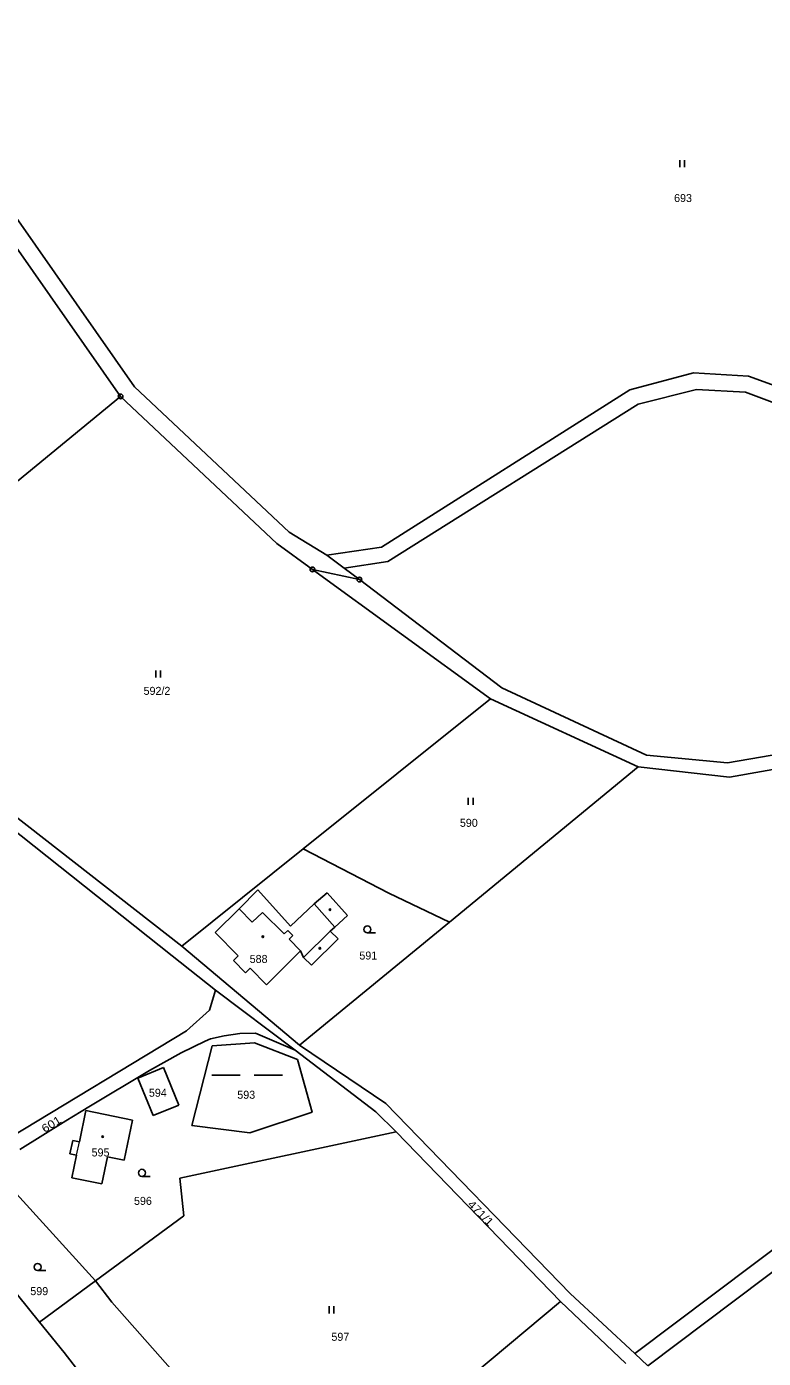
# Model space of a CAD drawing. Extents: x -727701 to -724405, y -960481 to -957284.
# Drawn here: x -726527.9 to -726371.3, y -958595.3 to -958312.4 of the extents above; entities that cross this region are included whole.
import ezdxf
from ezdxf.enums import TextEntityAlignment as Align

# ---------------------------------------------------------------- set-up
doc = ezdxf.new("R2010")
doc.units = 0
doc.header["$LTSCALE"] = 0.68
for name, color, linetype, lineweight in [('1', 7, 'Continuous', 25), ('3', 7, 'Continuous', 25), ('4', 7, 'Continuous', 13), ('5', 7, 'Continuous', 25), ('8', 7, 'Continuous', 25)]:
    doc.layers.add(name, color=color, linetype=linetype, lineweight=lineweight)
doc.layers.add('2', color=7, linetype='Continuous')

msp = doc.modelspace()

# ---------------------------------------------------------------- linework, layer by layer
at = {"layer": '1'}
for p, q in [((-726558.45, -958312.44), (-726504.95, -958388.96)), ((-726507.9, -958390.97), (-726543.34, -958340.44)), ((-726399.68, -958389.62), (-726386.17, -958385.97)), ((-726386.17, -958385.97), (-726374.48, -958386.65)), ((-726374.48, -958386.65), (-726360.77, -958391.64)), ((-726571.62, -958443.21), (-726507.9, -958390.97)), ((-726507.9, -958390.97), (-726474.73, -958422.21)), ((-726504.95, -958388.96), (-726472.1, -958419.8)), ((-726452.47, -958423.01), (-726399.68, -958389.62)), ((-726397.91, -958392.65), (-726385.51, -958389.49)), ((-726385.51, -958389.49), (-726375.11, -958390.09)), ((-726375.11, -958390.09), (-726362.44, -958394.84)), ((-726451.1, -958426.04), (-726397.91, -958392.65)), ((-726472.1, -958419.8), (-726464.07, -958424.73)), ((-726474.73, -958422.21), (-726467.14, -958427.73)), ((-726464.07, -958424.73), (-726452.47, -958423.01)), ((-726464.07, -958424.73), (-726460.38, -958427.44)), ((-726429.3, -958455.24), (-726467.14, -958427.73)), ((-726467.14, -958427.73), (-726457.14, -958429.9)), ((-726460.38, -958427.44), (-726451.1, -958426.04)), ((-726457.14, -958429.9), (-726460.38, -958427.44)), ((-726457.14, -958429.9), (-726426.91, -958452.91)), ((-726378.9, -958468.82), (-726269.95, -958449.87)), ((-726426.91, -958452.91), (-726396.12, -958467.2)), ((-726378.49, -958471.86), (-726270.02, -958452.75)), ((-726469.14, -958487.11), (-726429.3, -958455.24)), ((-726429.3, -958455.24), (-726397.95, -958469.69)), ((-726554.55, -958464.1), (-726496.91, -958509.8)), ((-726552.63, -958462.81), (-726494.91, -958507.72)), ((-726396.12, -958467.2), (-726378.9, -958468.82)), ((-726397.95, -958469.69), (-726438.04, -958502.68)), ((-726397.95, -958469.69), (-726378.49, -958471.86)), ((-726494.91, -958507.72), (-726469.14, -958487.11)), ((-726469.14, -958487.11), (-726450.93, -958496.46)), ((-726482.7, -958499.85), (-726478.75, -958495.8)), ((-726478.75, -958495.8), (-726471.77, -958503.5)), ((-726471.77, -958503.5), (-726466.74, -958498.76)), ((-726466.74, -958498.76), (-726464.01, -958496.42)), ((-726464.01, -958496.42), (-726459.68, -958501.24)), ((-726450.93, -958496.46), (-726438.04, -958502.68)), ((-726487.8, -958504.87), (-726482.7, -958499.85)), ((-726459.68, -958501.24), (-726462.36, -958503.7)), ((-726438.04, -958502.68), (-726469.86, -958528.75)), ((-726462.36, -958503.7), (-726463.35, -958504.58)), ((-726463.35, -958504.58), (-726461.67, -958506.2)), ((-726482.94, -958509.82), (-726487.8, -958504.87)), ((-726461.67, -958506.2), (-726467.31, -958511.82)), ((-726496.91, -958509.8), (-726487.75, -958517.12)), ((-726494.91, -958507.72), (-726469.86, -958528.75)), ((-726483.91, -958510.77), (-726482.94, -958509.82)), ((-726469.69, -958508.72), (-726476.92, -958515.96)), ((-726469, -958510.18), (-726469.69, -958508.72)), ((-726467.31, -958511.82), (-726469, -958510.18)), ((-726481.34, -958513.4), (-726483.91, -958510.77)), ((-726480.36, -958512.45), (-726481.34, -958513.4)), ((-726476.92, -958515.96), (-726480.36, -958512.45)), ((-726493.92, -958525.75), (-726488.99, -958521.32)), ((-726531.35, -958548.4), (-726493.92, -958525.75)), ((-726488.77, -958527.46), (-726489.96, -958527.91)), ((-726485.86, -958526.83), (-726488.77, -958527.46)), ((-726482.56, -958526.32), (-726485.86, -958526.83)), ((-726479.23, -958526.26), (-726482.56, -958526.32)), ((-726470.78, -958529.81), (-726479.23, -958526.26)), ((-726489.96, -958527.91), (-726495, -958530.43)), ((-726492.76, -958545.82), (-726488.41, -958528.92)), ((-726488.41, -958528.92), (-726479.45, -958528.28)), ((-726479.45, -958528.28), (-726470.3, -958531.8)), ((-726470.78, -958529.81), (-726453.64, -958542.93)), ((-726469.86, -958528.75), (-726451.57, -958541.16)), ((-726495, -958530.43), (-726501.78, -958534.16)), ((-726501.78, -958534.16), (-726514.65, -958541.88)), ((-726498.75, -958533.5), (-726504.21, -958535.81)), ((-726504.21, -958535.81), (-726501, -958543.7)), ((-726495.55, -958541.5), (-726498.75, -958533.5)), ((-726501, -958543.7), (-726495.55, -958541.5)), ((-726451.57, -958541.16), (-726412.36, -958581.56)), ((-726514.65, -958541.88), (-726519.54, -958544.82)), ((-726515.27, -958542.68), (-726516.65, -958549.31)), ((-726505.36, -958544.74), (-726515.27, -958542.68)), ((-726453.64, -958542.93), (-726449.34, -958547.18)), ((-726519.54, -958544.82), (-726529.33, -958550.91)), ((-726507.13, -958553.23), (-726505.36, -958544.74)), ((-726449.34, -958547.18), (-726495.33, -958557.02)), ((-726480.44, -958547.38), (-726492.76, -958545.82)), ((-726449.34, -958547.18), (-726414.39, -958583.23)), ((-726518.07, -958549.02), (-726518.66, -958551.85)), ((-726516.65, -958549.31), (-726518.07, -958549.02)), ((-726518.66, -958551.85), (-726517.24, -958552.15)), ((-726517.24, -958552.15), (-726518.24, -958556.93)), ((-726511.9, -958558.25), (-726510.7, -958552.49)), ((-726510.7, -958552.49), (-726507.13, -958553.23)), ((-726535.05, -958554.83), (-726513.21, -958578.81)), ((-726518.24, -958556.93), (-726511.9, -958558.25)), ((-726495.33, -958557.02), (-726494.44, -958565.01)), ((-726545.42, -958562.55), (-726525.15, -958587.59)), ((-726494.44, -958565.01), (-726513.21, -958578.81)), ((-726398.62, -958594.24), (-726363.66, -958567.96)), ((-726395.89, -958596.87), (-726361.41, -958570.91)), ((-726525.15, -958587.59), (-726513.21, -958578.81)), ((-726513.21, -958578.81), (-726509.75, -958583.4)), ((-726509.75, -958583.4), (-726471.19, -958626.87)), ((-726454.01, -958616.28), (-726414.39, -958583.23)), ((-726414.39, -958583.23), (-726400.54, -958596.41)), ((-726412.36, -958581.56), (-726398.62, -958594.24)), ((-726519.91, -958594.06), (-726525.15, -958587.59)), ((-726519.91, -958594.06), (-726516.08, -958599.05)), ((-726395.89, -958596.87), (-726398.62, -958594.24))]:
    msp.add_line(p, q, dxfattribs=at)
for points in [[(-726488.99, -958521.32), (-726487.75, -958517.12), (-726470.78, -958529.81)], [(-726470.3, -958531.8), (-726467.2, -958543.02), (-726480.44, -958547.38)]]:
    msp.add_lwpolyline(points, dxfattribs=at)
at = {"layer": '3'}
for p, q in [((-726389.051, -958342.3), (-726389.051, -958340.8)), ((-726388.05, -958342.3), (-726388.05, -958340.8)), ((-726500.431, -958450.69), (-726500.431, -958449.19)), ((-726499.43, -958450.69), (-726499.43, -958449.19)), ((-726434.011, -958477.76), (-726434.011, -958476.26)), ((-726433.01, -958477.76), (-726433.01, -958476.26)), ((-726455.453, -958504.94), (-726453.703, -958504.94)), ((-726488.509, -958535.16), (-726482.509, -958535.16)), ((-726479.509, -958535.16), (-726473.509, -958535.16)), ((-726503.363, -958556.65), (-726501.613, -958556.65)), ((-726525.533, -958576.65), (-726523.783, -958576.65)), ((-726463.611, -958585.75), (-726463.611, -958584.25)), ((-726462.61, -958585.75), (-726462.61, -958584.25))]:
    msp.add_line(p, q, dxfattribs=at)
for centre in [(-726455.4529, -958504.1898), (-726503.3629, -958555.8998), (-726525.5329, -958575.8998)]:
    msp.add_circle(centre, 0.75, dxfattribs=at)
at = {"layer": '4'}
for p, q in [((-726462.36, -958503.7), (-726466.74, -958498.76)), ((-726482.7, -958499.85), (-726479.95, -958502.65)), ((-726479.95, -958502.65), (-726477.75, -958500.6)), ((-726477.75, -958500.6), (-726473.15, -958505.15)), ((-726473.15, -958505.15), (-726472.35, -958504.45)), ((-726472.35, -958504.45), (-726471.3, -958505.5)), ((-726469, -958510.18), (-726463.35, -958504.58)), ((-726471.3, -958505.5), (-726472.1, -958506.3)), ((-726472.1, -958506.3), (-726469.69, -958508.72)), ((-726517.24, -958552.15), (-726516.65, -958549.31))]:
    msp.add_line(p, q, dxfattribs=at)
at = {"layer": '5'}
for centre in [(-726463.4068, -958500.0092), (-726477.6668, -958505.7392), (-726465.5468, -958508.2092), (-726511.7268, -958548.1992)]:
    msp.add_circle(centre, 0.175, dxfattribs=at)
at = {"layer": '8'}
for centre, radius in [((-726507.9, -958390.9699), 0.5), ((-726507.9, -958390.9699), 0.0303), ((-726467.14, -958427.7299), 0.5), ((-726467.14, -958427.7299), 0.0303), ((-726457.14, -958429.8999), 0.5), ((-726457.14, -958429.8999), 0.0303)]:
    msp.add_circle(centre, radius, dxfattribs=at)

# ---------------------------------------------------------------- texts
at = {"layer": '2'}
for s, p in [('693', (-726390.28, -958349.695)), ('590', (-726435.8, -958482.405)), ('588', (-726480.47, -958511.315)), ('591', (-726457.16, -958510.595)), ('593', (-726483.1, -958540.165)), ('595', (-726514.06, -958552.415)), ('596', (-726505.05, -958562.705)), ('599', (-726527.08, -958581.875)), ('597', (-726463.1, -958591.575))]:
    msp.add_text(s, height=1.7, dxfattribs=at).set_placement(p)
for s, p in [('592/2', (-726500.17, -958454.375)), ('594', (-726499.989, -958539.735))]:
    msp.add_text(s, height=1.7, dxfattribs=at).set_placement(p, align=Align.CENTER)
at = {"layer": '2', "width": 1.15}
msp.add_text('601', height=1.7, rotation=32, dxfattribs=at).set_placement((-726524.024, -958547.44))
msp.add_text('471/1', height=1.7, rotation=315, dxfattribs=at).set_placement((-726431.9835, -958565.0465), align=Align.CENTER)

doc.saveas('drawing.dxf')
